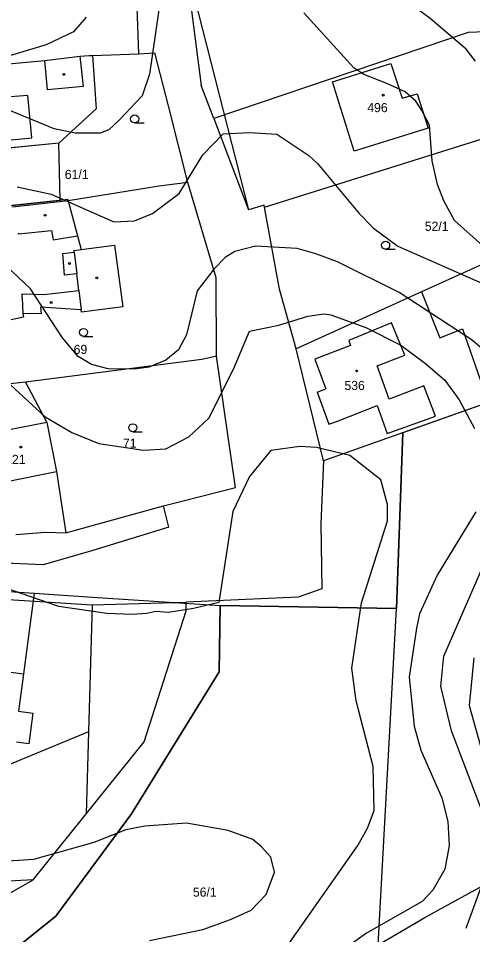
# Model space of a CAD drawing. Extents: x -555860 to -552701, y -1187050 to -1182291.
# Drawn here: x -554286.6 to -554201.9, y -1184633.4 to -1184462.7 of the extents above; entities that cross this region are included whole.
import ezdxf

# ---------------------------------------------------------------- set-up
doc = ezdxf.new("R2010")
doc.units = 0
for name, color, linetype in [('CYKLISTI_stav', 7, 'Continuous'), ('LEG_2b', 7, 'Continuous'), ('Level 25', 7, 'Continuous'), ('Level 32', 7, 'Continuous'), ('Level 40', 7, 'Continuous'), ('Level 41', 7, 'Continuous'), ('navrh_BV', 7, 'Continuous'), ('Poz předměty', 7, 'Continuous')]:
    doc.layers.add(name, color=color, linetype=linetype)

msp = doc.modelspace()

# ---------------------------------------------------------------- linework, layer by layer
at = {"layer": 'CYKLISTI_stav'}
for p, q in [((-554281.11, -1184476.01), (-554281.62, -1184470.54)), ((-554275.09, -1184469.78), (-554274.51, -1184475.41)), ((-554227.97, -1184474.51), (-554217.09, -1184471.11)), ((-554217.09, -1184471.11), (-554215.02, -1184477.6)), ((-554274.51, -1184475.41), (-554281.11, -1184476.01)), ((-554223.97, -1184487.46), (-554227.97, -1184474.51)), ((-554284.81, -1184477.06), (-554296.61, -1184478.01)), ((-554284.02, -1184484.94), (-554284.81, -1184477.06)), ((-554215.02, -1184477.6), (-554212.19, -1184476.76)), ((-554212.19, -1184476.76), (-554210.19, -1184483.17)), ((-554210.19, -1184483.17), (-554223.97, -1184487.46)), ((-554296.15, -1184486.12), (-554284.02, -1184484.94)), ((-554277.25, -1184496.73), (-554287.65, -1184497.87)), ((-554286.58, -1184502.66), (-554286.54, -1184502.85)), ((-554286.54, -1184502.85), (-554280.41, -1184502.2)), ((-554280.41, -1184502.2), (-554280.1, -1184503.97)), ((-554280.1, -1184503.97), (-554275.52, -1184503.21)), ((-554278.27, -1184506.53), (-554276.18, -1184506.26)), ((-554277.95, -1184510.58), (-554278.27, -1184506.53)), ((-554276.22, -1184505.97), (-554274.83, -1184505.78)), ((-554276.18, -1184506.26), (-554276.22, -1184505.97)), ((-554276.18, -1184506.26), (-554275.67, -1184510.29)), ((-554275.67, -1184510.29), (-554277.95, -1184510.58)), ((-554275.28, -1184513.41), (-554275.67, -1184510.29)), ((-554281.81, -1184514.14), (-554275.28, -1184513.41)), ((-554275.28, -1184513.41), (-554274.83, -1184517.03)), ((-554285.84, -1184514.8), (-554285.87, -1184514)), ((-554285.87, -1184514), (-554281.81, -1184514.14)), ((-554285.84, -1184514.8), (-554285.71, -1184517.67)), ((-554216.99, -1184519.46), (-554224.98, -1184522.7)), ((-554214.54, -1184525.48), (-554216.99, -1184519.46)), ((-554224.63, -1184523.64), (-554231.27, -1184526.2)), ((-554224.98, -1184522.7), (-554224.63, -1184523.64)), ((-554219.64, -1184527.47), (-554214.54, -1184525.48)), ((-554231.27, -1184526.2), (-554229.25, -1184531.75)), ((-554217.42, -1184533.64), (-554219.64, -1184527.47)), ((-554230.88, -1184532.33), (-554229.25, -1184531.75)), ((-554230.88, -1184532.33), (-554228.68, -1184538.31)), ((-554210.96, -1184531.18), (-554217.42, -1184533.64)), ((-554208.79, -1184536.83), (-554210.96, -1184531.18)), ((-554227.07, -1184537.73), (-554219.69, -1184534.85)), ((-554219.69, -1184534.85), (-554217.79, -1184540.06)), ((-554217.79, -1184540.06), (-554208.79, -1184536.83)), ((-554281.26, -1184537.97), (-554292.83, -1184540.24)), ((-554228.68, -1184538.31), (-554227.07, -1184537.73)), ((-554289.01, -1184549.05), (-554279.47, -1184547.15)), ((-554292.1, -1184584.02), (-554285.61, -1184584.84)), ((-554285.61, -1184584.84), (-554286.52, -1184591.77)), ((-554286.52, -1184591.77), (-554283.86, -1184592.12)), ((-554283.86, -1184592.12), (-554284.58, -1184597.84)), ((-554284.58, -1184597.84), (-554286.91, -1184597.54))]:
    msp.add_line(p, q, dxfattribs=at)
at = {"layer": 'Level 25'}
for p, q in [((-554264.88, -1184482.18), (-554263.13, -1184482.18)), ((-554218.09, -1184505.72), (-554216.34, -1184505.72)), ((-554274.4, -1184521.96), (-554272.65, -1184521.96)), ((-554265.22, -1184539.72), (-554263.47, -1184539.72))]:
    msp.add_line(p, q, dxfattribs=at)
for centre, radius in [((-554278.09, -1184473.14), 0.175), ((-554218.52, -1184477.03), 0.175), ((-554264.88, -1184481.43), 0.75), ((-554281.57, -1184499.4), 0.175), ((-554218.09, -1184504.97), 0.75), ((-554277.05, -1184508.37), 0.175), ((-554271.95, -1184511.05), 0.175), ((-554280.47, -1184515.66), 0.175), ((-554274.4, -1184521.21), 0.75), ((-554223.49, -1184528.4), 0.175), ((-554265.22, -1184538.97), 0.75), ((-554286.08, -1184542.57), 0.175)]:
    msp.add_circle(centre, radius, dxfattribs=at)
at = {"layer": 'Level 32'}
for points in [[(-554171.95, -1184475.96), (-554184.23, -1184479.8), (-554175.48, -1184497.33), (-554170.58, -1184509.11), (-554156.08, -1184515.36), (-554181.64, -1184528.14), (-554214.89, -1184539.93), (-554216.08, -1184572.66), (-554248.93, -1184572.12), (-554249.13, -1184584.47)], [(-554302.1, -1184488.23), (-554302.55, -1184483.6), (-554303.75, -1184483.72), (-554304.39, -1184495.53), (-554299.48, -1184495.83), (-554298.19, -1184495.53), (-554297.67, -1184500.1), (-554292.86, -1184498.59), (-554287.71, -1184497.57), (-554278.79, -1184496.59), (-554279.04, -1184485.94), (-554302.1, -1184488.23)], [(-554249.13, -1184584.47), (-554265.44, -1184610.89), (-554279.6, -1184629.99), (-554323.09, -1184664.88), (-554334.59, -1184685.99), (-554344.83, -1184692.69), (-554356.21, -1184692.69), (-554360.55, -1184707.77), (-554357.64, -1184711.84), (-554347.4, -1184712.36)]]:
    msp.add_lwpolyline(points, dxfattribs=at)
at = {"layer": 'Level 40'}
for points in [[(-554294.43, -1184525.13), (-554281.54, -1184536.92), (-554276.6, -1184539.89), (-554271.55, -1184541.91), (-554263.23, -1184543.16), (-554259.07, -1184542.88), (-554254.78, -1184540.66), (-554251.03, -1184537.19), (-554246.46, -1184528.04), (-554243.44, -1184521.01), (-554238.03, -1184519.89), (-554232.62, -1184518.21), (-554229.61, -1184517.78), (-554228.29, -1184517.92), (-554221.78, -1184520.28), (-554215.26, -1184523.6), (-554210.63, -1184527.02), (-554207.08, -1184530.12), (-554204.36, -1184533.78), (-554201.53, -1184539.13)], [(-554201.25, -1184554.66), (-554208.46, -1184566.45), (-554211.79, -1184573.66), (-554212.35, -1184576.29), (-554213.73, -1184585.45), (-554212.76, -1184594.6), (-554211.52, -1184599.03), (-554207.63, -1184607.91), (-554206.52, -1184612.34), (-554206.25, -1184616.78), (-554207.08, -1184621.22), (-554209.28, -1184625.12), (-554211.26, -1184627.26), (-554221.64, -1184633.14), (-554227.76, -1184637.49)]]:
    msp.add_lwpolyline(points, dxfattribs=at)
at = {"layer": 'Level 41'}
for points in [[(-554258.11, -1184445.63), (-554262.12, -1184473.13), (-554263.51, -1184477.16), (-554267.69, -1184481.64), (-554269.67, -1184483.45), (-554271.28, -1184484.09), (-554275.94, -1184484.11), (-554279.87, -1184483.26), (-554288.75, -1184479.65)], [(-554201.36, -1184470.69), (-554203.1, -1184468.42), (-554209.76, -1184462.73), (-554215.71, -1184458.31)], [(-554273.91, -1184462.46), (-554276.27, -1184465.23), (-554281.39, -1184467.61), (-554288.19, -1184469.67)], [(-554198.29, -1184506.58), (-554205.23, -1184500.34), (-554207.21, -1184496.69), (-554208.42, -1184493.68), (-554209.39, -1184489.25), (-554209.94, -1184482.59), (-554211.33, -1184479.86), (-554212.44, -1184478.16), (-554214.47, -1184476.4), (-554217.84, -1184474.83), (-554222.14, -1184473.16), (-554224.04, -1184471.94), (-554233.37, -1184461.65)], [(-554286.81, -1184494.07), (-554280.43, -1184495.46), (-554268.78, -1184500.59), (-554264.9, -1184500.45), (-554261.57, -1184499.06), (-554256.58, -1184495.32), (-554252.14, -1184488.11), (-554248.4, -1184484.23), (-554243.47, -1184483.95), (-554238.35, -1184484.28), (-554232.42, -1184488.24), (-554230.79, -1184489.77), (-554223.02, -1184499.06), (-554220.37, -1184501.77), (-554215.81, -1184505.16), (-554199.73, -1184512.24)], [(-554197.65, -1184526.38), (-554201.95, -1184522.63), (-554215.54, -1184513.76), (-554227.05, -1184508.07), (-554231.09, -1184506.55), (-554234.56, -1184505.56), (-554242.32, -1184505.14), (-554246.18, -1184506.13), (-554247.98, -1184507.24), (-554250.04, -1184509.36), (-554253.25, -1184513.48), (-554255.19, -1184521.66), (-554256.72, -1184524.44), (-554259.07, -1184526.38), (-554262.25, -1184527.68), (-554264.9, -1184528.04), (-554269.84, -1184528), (-554272.94, -1184527.21), (-554275.44, -1184525.68), (-554278.35, -1184522.22), (-554284.31, -1184513.07), (-554288.89, -1184508.77)], [(-554236.89, -1184636.19), (-554223.3, -1184616.78), (-554221.49, -1184613.57), (-554220.25, -1184610.26), (-554220.39, -1184602.08), (-554223.58, -1184589.88), (-554224.41, -1184583.78), (-554222.61, -1184571.58), (-554217.76, -1184556.33), (-554217.76, -1184553.28), (-554219, -1184548.7), (-554224.79, -1184544.13), (-554230.95, -1184542.64), (-554234.11, -1184542.45), (-554239.52, -1184543.2), (-554243.44, -1184548.05), (-554246.6, -1184554.58), (-554249.21, -1184571.55), (-554253.88, -1184572.67), (-554258.54, -1184573.41), (-554260.96, -1184573.23), (-554262.64, -1184573.6), (-554265.43, -1184573.79), (-554270.09, -1184573.6), (-554279.04, -1184572.29), (-554289.29, -1184568.75)], [(-554199.45, -1184612.07), (-554205.83, -1184595.43), (-554207.77, -1184587.11), (-554207.22, -1184581.56), (-554195.99, -1184555.77)], [(-554201.67, -1184581.84), (-554202.5, -1184590.71), (-554200.01, -1184599.59)], [(-554262.12, -1184634.53), (-554252.14, -1184632.45), (-554247.04, -1184630.56), (-554243.13, -1184628.84), (-554240.36, -1184625.93), (-554238.83, -1184621.77), (-554239.52, -1184619), (-554241.26, -1184617.03), (-554242.85, -1184615.67), (-554247.43, -1184614.01), (-554255.19, -1184612.62), (-554262.96, -1184613.18), (-554266.51, -1184613.9), (-554272.52, -1184616.23), (-554283.76, -1184619.42), (-554290.41, -1184619.83)], [(-554203.06, -1184632.18), (-554198.99, -1184620.96)]]:
    msp.add_lwpolyline(points, dxfattribs=at)
at = {"layer": 'navrh_BV'}
for p, q in [((-554264.12, -1184469.34), (-554264.75, -1184449.36)), ((-554254.97, -1184455.88), (-554252.45, -1184475.23)), ((-554202.68, -1184465.32), (-554250.12, -1184481.37)), ((-554176.05, -1184464.53), (-554202.68, -1184465.32)), ((-554272.72, -1184469.6), (-554264.12, -1184469.34)), ((-554264.12, -1184469.34), (-554261.11, -1184469.11)), ((-554258.6, -1184479), (-554261.11, -1184469.11)), ((-554300.14, -1184472.21), (-554281.62, -1184470.54)), ((-554281.62, -1184470.54), (-554275.09, -1184469.78)), ((-554275.09, -1184469.78), (-554273.35, -1184469.62)), ((-554273.35, -1184469.62), (-554272.72, -1184469.6)), ((-554272.72, -1184469.6), (-554272.08, -1184479.58)), ((-554250.12, -1184481.37), (-554252.45, -1184475.23)), ((-554272.08, -1184479.58), (-554279.04, -1184485.94)), ((-554254.99, -1184493.26), (-554258.6, -1184479)), ((-554250.12, -1184481.37), (-554243.67, -1184498.4)), ((-554240.69, -1184497.86), (-554195.86, -1184483.82)), ((-554279.04, -1184485.94), (-554302.1, -1184488.23)), ((-554254.99, -1184493.26), (-554260.3, -1184493.99)), ((-554249.7, -1184511.06), (-554254.99, -1184493.26)), ((-554260.3, -1184493.99), (-554277.25, -1184496.73)), ((-554277.29, -1184496.43), (-554287.71, -1184497.57)), ((-554277.25, -1184496.73), (-554277.29, -1184496.43)), ((-554277.25, -1184496.73), (-554275.52, -1184503.21)), ((-554240.76, -1184497.49), (-554243.67, -1184498.4)), ((-554240.69, -1184497.86), (-554240.76, -1184497.49)), ((-554237.89, -1184513.13), (-554240.69, -1184497.86)), ((-554175.48, -1184497.33), (-554211.42, -1184513.66)), ((-554275.52, -1184503.21), (-554274.83, -1184505.78)), ((-554274.83, -1184505.78), (-554268.63, -1184504.96)), ((-554268.63, -1184504.96), (-554267.1, -1184516.45)), ((-554249.63, -1184525.64), (-554249.7, -1184511.06)), ((-554234.79, -1184524.28), (-554237.89, -1184513.13)), ((-554211.42, -1184513.66), (-554234.79, -1184524.28)), ((-554211.42, -1184513.66), (-554207.99, -1184522.24)), ((-554274.83, -1184517.03), (-554282.46, -1184516.54)), ((-554282.46, -1184516.54), (-554282.31, -1184517.77)), ((-554274.78, -1184517.42), (-554274.83, -1184517.03)), ((-554267.1, -1184516.45), (-554274.78, -1184517.42)), ((-554285.63, -1184518.37), (-554292.61, -1184519.93)), ((-554282.31, -1184517.77), (-554285.71, -1184517.67)), ((-554285.71, -1184517.67), (-554285.63, -1184518.37)), ((-554207.99, -1184522.24), (-554203.78, -1184520.55)), ((-554203.78, -1184520.55), (-554198.99, -1184534.29)), ((-554249.63, -1184525.64), (-554252.33, -1184526.27)), ((-554246.11, -1184550.09), (-554249.63, -1184525.64)), ((-554229.66, -1184545.16), (-554234.79, -1184524.28)), ((-554252.33, -1184526.27), (-554285.24, -1184530.47)), ((-554285.24, -1184530.47), (-554290.33, -1184531.03)), ((-554285.24, -1184530.47), (-554281.26, -1184537.97)), ((-554198.99, -1184534.29), (-554229.66, -1184545.16)), ((-554281.26, -1184537.97), (-554279.47, -1184547.15)), ((-554229.66, -1184545.16), (-554230.17, -1184556.9)), ((-554279.47, -1184547.15), (-554277.69, -1184558.54)), ((-554259.53, -1184553.55), (-554246.11, -1184550.09)), ((-554277.69, -1184558.54), (-554259.53, -1184553.55)), ((-554258.53, -1184557.5), (-554259.53, -1184553.55)), ((-554258.53, -1184557.5), (-554272.69, -1184561.84)), ((-554230.17, -1184556.9), (-554229.98, -1184568.98)), ((-554287.02, -1184558.89), (-554281.5, -1184558.42)), ((-554281.5, -1184558.42), (-554277.69, -1184558.54)), ((-554272.69, -1184561.84), (-554281.94, -1184564.49)), ((-554281.94, -1184564.49), (-554298.16, -1184563.78)), ((-554346.67, -1184567.43), (-554272.79, -1184571.95)), ((-554229.98, -1184568.98), (-554234.37, -1184570.52)), ((-554272.79, -1184571.95), (-554255.27, -1184571.44)), ((-554255.29, -1184573.11), (-554255.27, -1184571.44)), ((-554234.37, -1184570.52), (-554255.27, -1184571.44)), ((-554272.79, -1184571.95), (-554273.46, -1184595.6)), ((-554263.12, -1184597.5), (-554255.29, -1184573.11)), ((-554273.46, -1184595.6), (-554298.54, -1184606.01)), ((-554283.78, -1184623.18), (-554263.12, -1184597.5)), ((-554294.91, -1184629.51), (-554283.78, -1184623.18)), ((-554210.79, -1184630.22), (-554198.24, -1184623.33)), ((-554219.51, -1184635.3), (-554210.79, -1184630.22))]:
    msp.add_line(p, q, dxfattribs=at)
at = {"layer": 'Poz předměty'}
for points in [[(-554254.62, -1184455.48), (-554243.67, -1184498.4)], [(-554360.55, -1184707.77), (-554356.21, -1184692.69), (-554344.83, -1184692.69), (-554334.59, -1184685.99), (-554323.09, -1184664.88), (-554279.6, -1184629.99), (-554265.44, -1184610.89), (-554249.13, -1184584.47), (-554248.93, -1184572.12), (-554216.08, -1184572.66), (-554214.89, -1184539.93)], [(-554346.56, -1184565.62), (-554332.42, -1184566.56), (-554283.64, -1184569.81), (-554272.74, -1184570.53)], [(-554283.64, -1184569.81), (-554285.61, -1184584.84)], [(-554272.74, -1184570.53), (-554248.93, -1184572.12)], [(-554219.51, -1184635.3), (-554216.08, -1184572.66)], [(-554273.46, -1184595.6), (-554273.9, -1184610.9)], [(-554283.78, -1184623.18), (-554312.32, -1184624.73)]]:
    msp.add_lwpolyline(points, dxfattribs=at)

# ---------------------------------------------------------------- texts
at = {"layer": 'LEG_2b'}
for s, p in [('496', (-554221.51, -1184480.18)), ('61/1', (-554277.9, -1184492.62)), ('52/1', (-554210.79, -1184502.29)), ('69', (-554276.25, -1184525.23)), ('536', (-554225.77, -1184531.95)), ('71', (-554267.07, -1184542.7)), ('121', (-554289.01, -1184545.72)), ('56/1', (-554254.02, -1184626.33))]:
    msp.add_text(s, height=1.7, dxfattribs=at).set_placement(p)

doc.saveas('drawing.dxf')
